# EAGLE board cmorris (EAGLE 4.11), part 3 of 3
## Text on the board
tPlace: 1 | 1 | 1 | 8 | 8 | 8 | 10 | 10 | 10 | 10 | 10 | 10 | 10 | 1 | 1 | 1 | 1 | 1 | 1 | 1
tNames: C10 | C10 | C10 | C10 | DF32x4 Disk Emulator Rev. B (c)2003 CEMorris | DF32x4 Disk Emulator Rev. B (c)2003 CEMorris | GND | GND | GND | +5V | +5V | +5V | C1 | C1 | C1 | C1 | C1 | C1 | C1 | R3 | R3 | R3 | R4 | R4 | R4 | IC17 | IC17 | IC17 | IC17 | IC17 | IC17 | IC17 | R5 | R5 | R5 | SV3 | SV3 | SV3 | SV3 | SV3 | SV3 | SV3 | C7 | C7 | C7 | C5 | C5 | C5 | IC22 | IC22 | IC22 | IC12 | IC12 | IC12 | IC12 | IC12 | IC12 | IC12 | C7 | C7 | C7 | C7 | IC11 | IC11 | IC11 | IC24 | IC24 | IC24 | IC24 | IC24 | IC24 | IC24 | C3 | C3 | C3 | C3 | C3 | C3 | C3 | C9 | C9 | C9 | C9 | C9 | C9 | C9 | R2 | R2 | R2
tValues: 220 | 220 | 220 | 220 | 220 | 220 | 220 | 220 | 220 | 220 | SE14 | SE14 | SE14 | SE14 | SE14 | SE14 | SE14 | SE14 | SE14 | SE14 | SE14 | SE14 | SE14 | SE14 | 220 | 220 | 220 | PANEL LEDS | PANEL LEDS | PANEL LEDS | DS1258 | DS1258 | DS1258 | DS1258 | DS1258 | DS1258 | DS1258 | WRLOCK | WRLOCK | WRLOCK | WRLOCK | WRLOCK | WRLOCK | WRLOCK | 74LS30N | 74LS30N | 74LS30N | 74LS30N | 74LS30N | 74LS30N | 74LS30N | 74LS191N | 74LS191N | 74LS191N | 74LS191N | 74LS191N | 74LS191N | 74LS191N | 74LS191N | 74LS191N | 74LS191N | 74LS191N | 74LS191N | 74LS191N | 74LS191N | 74LS155N | 74LS155N | 74LS155N | 74LS155N | 74LS155N | 74LS155N | 74LS155N | 74LS155N | 74LS155N | 74LS155N | 74LS155N | 74LS155N | 74LS155N | 74LS155N | 74LS138N | 74LS138N | 74LS138N | 74LS138N | 74LS138N | 74LS138N | 74LS138N | 74LS191N | 74LS191N | 74LS191N | 74LS191N | 74LS191N | 74LS191N | 74LS191N | 74LS191N | 74LS191N | 74LS191N | 74LS191N | 74LS191N | 74LS191N | 74LS191N | 74LS191N | 74LS191N | 74LS191N | 74LS191N | 74LS191N | 74LS191N | 74LS191N | 10K | 10K | 10K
